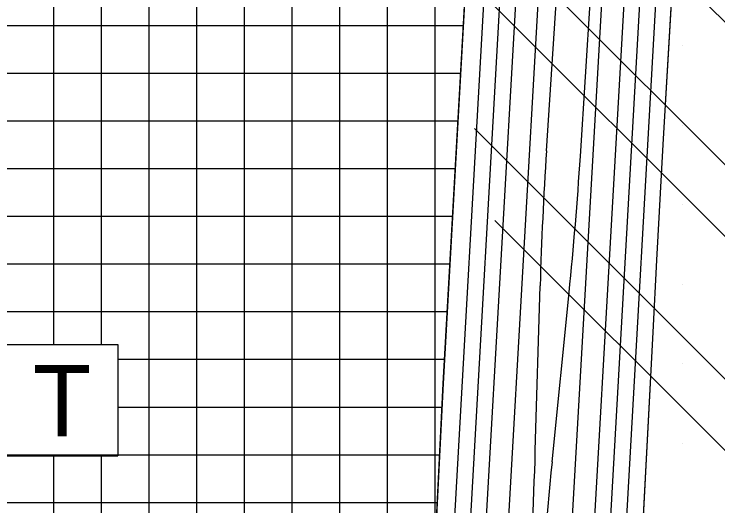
# Model space of a CAD drawing. Extents: x 419109 to 421295, y 4452223 to 4457798.
# Drawn here: x 420079.2 to 420300.6, y 4455575.7 to 4455730.3 of the extents above; entities that cross this region are included whole.
import ezdxf

# ---------------------------------------------------------------- set-up
doc = ezdxf.new("R2010")
doc.units = 0
for name, color, linetype in [('ADAKENARI', 7, 'Continuous'), ('KALDIRIM_FAT', 7, 'Continuous'), ('PL_KAMU_HİZMET_ALANI', 7, 'Continuous'), ('PL_TİCARET', 7, 'Continuous'), ('RAYLI_TOPLU_TAŞIMA_HATTI', 7, 'Continuous'), ('SEMBOL_FAT', 7, 'Continuous'), ('SN_TR_SIVILASMA', 7, 'Continuous'), ('TRFAT_KHA', 7, 'Continuous'), ('TRFAT_TİCARET', 7, 'Continuous')]:
    doc.layers.add(name, color=color, linetype=linetype)

msp = doc.modelspace()

# ---------------------------------------------------------------- linework, layer by layer
at = {"layer": 'ADAKENARI'}
for p, q in [((420222.97, 4455770), (420214.19, 4455614.16)), ((420283.41, 4455689.36), (420287.76, 4455764.57)), ((420281.42, 4455652.94), (420283.41, 4455689.36)), ((420280.18, 4455630.34), (420281.42, 4455652.94)), ((420275.69, 4455544.7), (420280.18, 4455630.34)), ((420214.19, 4455614.16), (420211.61, 4455562.8))]:
    msp.add_line(p, q, dxfattribs=at)
at = {"layer": 'KALDIRIM_FAT'}
for p, q in [((420234.15, 4455861.94), (420215.94, 4455540.77)), ((420239.14, 4455861.63), (420220.93, 4455540.45)), ((420244.13, 4455861.32), (420225.92, 4455540.14)), ((420251.12, 4455860.89), (420232.91, 4455539.7)), ((420271.08, 4455859.65), (420252.87, 4455538.43)), ((420278.07, 4455859.22), (420259.85, 4455537.99)), ((420283.06, 4455858.91), (420264.84, 4455537.67)), ((420288.05, 4455858.6), (420269.83, 4455537.36))]:
    msp.add_line(p, q, dxfattribs=at)
at = {"layer": 'PL_KAMU_HİZMET_ALANI'}
msp.add_lwpolyline([(420264.37, 4455372.95), (420265.19, 4455389.09), (420271.14, 4455474.52), (420272.42, 4455492.95), (420275.69, 4455544.7), (420280.18, 4455630.34), (420281.42, 4455652.94), (420283.41, 4455689.36), (420287.76, 4455764.57), (420292.21, 4455838.27), (420294.94, 4455879.49), (420299.25, 4455948.07), (420304.91, 4456025.25)], dxfattribs=at)
at = {"layer": 'PL_TİCARET'}
msp.add_lwpolyline([(420199.15, 4455373.07), (420200.5, 4455392.26), (420204.72, 4455452.72), (420207.73, 4455496.12), (420207.73, 4455496.12), (420172.52, 4455509.54), (420172.52, 4455509.54), (420190.39, 4455549.96), (420195.36, 4455552.2), (420210.57, 4455543.27), (420211.61, 4455562.8), (420214.19, 4455614.16), (420222.97, 4455770), (420224.17, 4455789.96), (420227.34, 4455842.37), (420228.66, 4455862.28), (420230.08, 4455883.68), (420231.44, 4455905.4), (420232.85, 4455927.79), (420233.94, 4455946.2), (420234.4, 4455952.49), (420240.06, 4456029.71)], dxfattribs=at)
at = {"layer": 'RAYLI_TOPLU_TAŞIMA_HATTI'}
for p, q in [((420246.66, 4455687.36), (420267.77, 4456014)), ((420257.33, 4455685.64), (420278.51, 4456013.3)), ((420243.16, 4455593.11), (420244.67, 4455644.92)), ((420248.43, 4455589.54), (420253.79, 4455642.74))]:
    msp.add_line(p, q, dxfattribs=at)
for centre, radius, start, end in [((421444.16, 4455609.96), 1200, 176.3021, 178.33048), ((419059.83, 4455763.03), 1200, 354.24653, 356.3021), ((419043.67, 4455628.07), 1200, 355.86092, 358.33048), ((422238.35, 4455389.05), 2000, 174.24653, 175.86092)]:
    msp.add_arc(centre, radius, start, end, dxfattribs=at)
at = {"layer": 'SEMBOL_FAT'}
for p, q in [((420076.85, 4455626.43), (420111.85, 4455626.43)), ((420111.85, 4455626.43), (420111.85, 4455591.43)), ((420076.85, 4455591.43), (420111.85, 4455591.43))]:
    msp.add_line(p, q, dxfattribs=at)
at = {"layer": 'SN_TR_SIVILASMA'}
for p, q in [((421028.68, 4455001.92), (420190.02, 4455840.58)), ((420983.3, 4455002.39), (420204.76, 4455780.94)), ((420960.61, 4455002.63), (420211.17, 4455752.07)), ((420915.23, 4455003.11), (420224, 4455694.34)), ((420892.54, 4455003.35), (420230.42, 4455665.47))]:
    msp.add_line(p, q, dxfattribs=at)
at = {"layer": 'TRFAT_KHA'}
for p, q in [((420289.37, 4455720.38), (420289.37, 4455720.38)), ((420289.37, 4455695.38), (420289.37, 4455695.38)), ((420289.37, 4455670.38), (420289.37, 4455670.38)), ((420289.37, 4455645.38), (420289.37, 4455645.38)), ((420289.37, 4455620.38), (420289.37, 4455620.38)), ((420289.37, 4455595.38), (420289.37, 4455595.38))]:
    msp.add_line(p, q, dxfattribs=at)
at = {"layer": 'TRFAT_TİCARET'}
for p, q in [((420211.68, 4455564.25), (420211.68, 4456103.64)), ((420196.68, 4455551.43), (420196.68, 4456082.02)), ((420181.68, 4455530.26), (420181.68, 4456045.72)), ((420166.68, 4455199.52), (420166.68, 4456009.42)), ((420151.68, 4455202.28), (420151.68, 4455965.68)), ((420136.68, 4455205.03), (420136.68, 4455929.15)), ((420121.68, 4455207.79), (420121.68, 4455897.66)), ((420106.68, 4455626.43), (420106.68, 4455866.37)), ((420091.68, 4455626.43), (420091.68, 4455835.08)), ((420039.24, 4455726.77), (420220.53, 4455726.77)), ((420030.96, 4455711.77), (420219.69, 4455711.77)), ((420022.68, 4455696.77), (420218.84, 4455696.77)), ((420014.4, 4455681.77), (420218, 4455681.77)), ((420006.12, 4455666.77), (420217.15, 4455666.77)), ((419997.85, 4455651.77), (420216.31, 4455651.77)), ((419989.57, 4455636.77), (420215.47, 4455636.77)), ((420111.85, 4455621.77), (420214.62, 4455621.77)), ((420111.85, 4455606.77), (420213.82, 4455606.77)), ((419964.73, 4455591.77), (420213.06, 4455591.77)), ((420091.68, 4455212.55), (420091.68, 4455591.43)), ((420106.68, 4455210.47), (420106.68, 4455591.43)), ((419956.45, 4455576.77), (420212.31, 4455576.77))]:
    msp.add_line(p, q, dxfattribs=at)

# ---------------------------------------------------------------- texts
at = {"layer": 'SEMBOL_FAT'}
msp.add_text('T', height=22.5, dxfattribs=at).set_placement((420085.14, 4455597.5))

doc.saveas('drawing.dxf')
